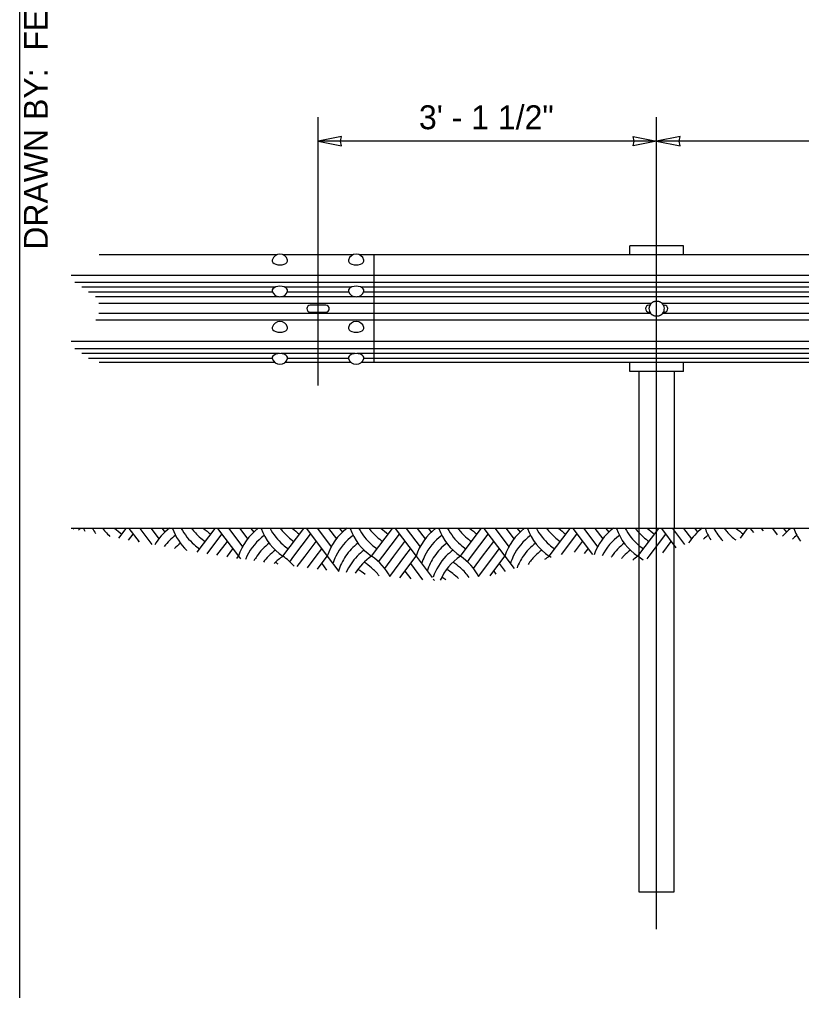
# Model space of a CAD drawing. Extents: x 99862 to 103680, y 99470 to 102076.
# Drawn here: x 99862 to 100385, y 100777 to 101426 of the extents above; entities that cross this region are included whole.
import ezdxf

# ---------------------------------------------------------------- set-up
doc = ezdxf.new("R2010")
doc.units = 0
for name, color, linetype in [('Level 1', 7, 'Continuous'), ('Level 14', 7, 'Continuous'), ('Level 15', 7, 'Continuous'), ('Level 2', 7, 'Continuous'), ('Level 20', 7, 'Continuous'), ('Level 27', 7, 'Continuous'), ('Level 4', 7, 'Continuous'), ('Level 62', 7, 'Continuous'), ('Level 7', 7, 'Continuous')]:
    doc.layers.add(name, color=color, linetype=linetype)

msp = doc.modelspace()

# ---------------------------------------------------------------- linework, layer by layer
at = {"layer": 'Level 1'}
msp.add_lwpolyline([(99862, 99999.5), (103151, 99999.5), (103151, 102075.5), (99862, 102075.5)], close=True, dxfattribs=at)
at = {"layer": 'Level 14'}
for p, q in [((100061.81, 101181.24), (100061.81, 101360.59)), ((100288.31, 100817.51), (100288.31, 101360.59)), ((102045.91, 101085.68), (99896.57, 101085.68)), ((99898.07, 101085.68), (99898.41, 101085.22)), ((99928.55, 101079.12), (99933.46, 101085.68)), ((99935.19, 101085.68), (99942.03, 101076.55)), ((99942.61, 101085.68), (99950.65, 101074.97)), ((99950.04, 101085.68), (99955.29, 101078.67)), ((99957.46, 101085.68), (99959.37, 101083.13)), ((99980.91, 101069.75), (99992.86, 101085.68)), ((99994.58, 101085.68), (100008.57, 101067.03)), ((100002.01, 101085.68), (100011.25, 101073.36)), ((100009.43, 101085.68), (100014.69, 101078.67)), ((100016.86, 101085.68), (100018.77, 101083.13)), ((100038.27, 101067.03), (100052.26, 101085.68)), ((100053.98, 101085.68), (100067.97, 101067.03)), ((100061.4, 101085.68), (100070.64, 101073.36)), ((100068.83, 101085.68), (100074.09, 101078.67)), ((100076.25, 101085.68), (100078.16, 101083.13)), ((100097.66, 101067.03), (100111.65, 101085.68)), ((100113.38, 101085.68), (100127.36, 101067.03)), ((100120.8, 101085.68), (100130.04, 101073.36)), ((100128.23, 101085.68), (100133.48, 101078.67)), ((100135.65, 101085.68), (100137.56, 101083.13)), ((100157.06, 101067.03), (100171.05, 101085.68)), ((100172.77, 101085.68), (100186.76, 101067.03)), ((100180.2, 101085.68), (100189.43, 101073.36)), ((100187.62, 101085.68), (100192.88, 101078.67)), ((100195.05, 101085.68), (100196.95, 101083.13)), ((100216.46, 101067.03), (100230.44, 101085.68)), ((100232.17, 101085.68), (100245.34, 101068.11)), ((100239.59, 101085.68), (100248.83, 101073.36)), ((100247.02, 101085.68), (100252.27, 101078.67)), ((100254.44, 101085.68), (100256.35, 101083.13)), ((100275.85, 101067.03), (100289.84, 101085.68)), ((100291.56, 101085.68), (100301.28, 101072.72)), ((100298.99, 101085.68), (100307.05, 101074.93)), ((100306.41, 101085.68), (100311.67, 101078.67)), ((100313.84, 101085.68), (100315.75, 101083.13)), ((100344.34, 101079.16), (100349.24, 101085.68)), ((100350.96, 101085.68), (100353.12, 101082.8)), ((100358.38, 101085.68), (100359.59, 101084.08)), ((100365.81, 101085.68), (100369.01, 101081.41)), ((100373.23, 101085.68), (100375.14, 101083.13)), ((99935.03, 101077.87), (99938.04, 101081.88)), ((99987.54, 101068.68), (99997.43, 101081.88)), ((100045.69, 101067.03), (100056.83, 101081.88)), ((100105.09, 101067.03), (100116.23, 101081.88)), ((100164.49, 101067.03), (100175.62, 101081.88)), ((100224.68, 101068.1), (100235.02, 101081.88)), ((100283.28, 101067.03), (100294.41, 101081.88)), ((99941.54, 101076.64), (99941.75, 101076.93)), ((99994.18, 101067.63), (100001.15, 101076.93)), ((100001.15, 101067.03), (100004.86, 101071.98)), ((100053.12, 101067.03), (100060.54, 101076.93)), ((100060.54, 101067.03), (100064.26, 101071.98)), ((100112.51, 101067.03), (100119.94, 101076.93)), ((100119.94, 101067.03), (100123.65, 101071.98)), ((100171.91, 101067.03), (100179.33, 101076.93)), ((100179.33, 101067.03), (100183.05, 101071.98)), ((100233.36, 101069.77), (100238.73, 101076.93)), ((100240.09, 101068.84), (100242.44, 101071.98)), ((100292.44, 101069.34), (100298.13, 101076.93)), ((100000.83, 101066.61), (100001.15, 101067.03)), ((100007.51, 101065.61), (100008.57, 101067.03)), ((100008.57, 101067.03), (100009.9, 101065.25)), ((100042.92, 101063.34), (100045.69, 101067.03)), ((100047.9, 101060.07), (100053.12, 101067.03)), ((100054.69, 101059.23), (100060.54, 101067.03)), ((100061.5, 101058.41), (100067.97, 101067.03)), ((100067.97, 101067.03), (100075.65, 101056.78)), ((100102.32, 101063.34), (100105.09, 101067.03)), ((100106.4, 101058.87), (100112.51, 101067.03)), ((100109.84, 101053.56), (100119.94, 101067.03)), ((100116.58, 101052.65), (100127.36, 101067.03)), ((100127.36, 101067.03), (100138.12, 101052.69)), ((100161.72, 101063.34), (100164.49, 101067.03)), ((100165.79, 101058.87), (100171.91, 101067.03)), ((100169.24, 101053.56), (100179.33, 101067.03)), ((100177, 101054.02), (100186.76, 101067.03)), ((100186.76, 101067.03), (100193, 101058.71)), ((100282.03, 101065.37), (100283.28, 101067.03)), ((100064.26, 101062.08), (100067.54, 101057.7)), ((100123.65, 101062.08), (100131.71, 101051.34)), ((100183.05, 101062.08), (100186.92, 101056.91)), ((100119.94, 101057.13), (100123.78, 101052.01)), ((100179.33, 101057.13), (100180.85, 101055.11)), ((100138.91, 101051.63), (100139.62, 101050.69))]:
    msp.add_line(p, q, dxfattribs=at)
for centre, start, end in [((99925.59, 101055.64), 126.9281, 129.9167), ((99940.44, 101098.22), 199.49222, 202.68252), ((99944.15, 101103.17), 207.73613, 213.8389), ((99947.86, 101108.12), 216.66402, 220.94161), ((99951.57, 101113.07), 226.78948, 236.09639), ((99984.99, 101055.64), 126.9281, 149.66125), ((99999.83, 101098.22), 199.49222, 226.66561), ((100003.55, 101103.17), 207.73613, 228.95992), ((100007.26, 101108.12), 216.66402, 220.94161), ((100010.97, 101113.07), 226.78948, 236.09639), ((100044.38, 101055.64), 126.9281, 162.3566), ((100059.23, 101098.22), 199.49222, 236.09639), ((100062.94, 101103.17), 207.73613, 228.95992), ((100066.66, 101108.12), 216.66402, 220.94161), ((100070.37, 101113.07), 226.78948, 236.09639), ((100103.78, 101055.64), 126.9281, 162.3566), ((100118.63, 101098.22), 199.49222, 236.09639), ((100122.34, 101103.17), 207.73613, 228.95992), ((100126.05, 101108.12), 216.66402, 220.94161), ((100129.76, 101113.07), 226.78948, 236.09639), ((100163.17, 101055.64), 126.9281, 162.3566), ((100178.02, 101098.22), 199.49222, 236.09639), ((100181.73, 101103.17), 207.73613, 228.95992), ((100185.45, 101108.12), 216.66402, 220.94161), ((100189.16, 101113.07), 226.78948, 236.09639), ((100222.57, 101055.64), 126.9281, 162.3566), ((100237.42, 101098.22), 199.49222, 236.09639), ((100241.13, 101103.17), 207.73613, 228.95992), ((100244.84, 101108.12), 216.66402, 220.94161), ((100248.55, 101113.07), 226.78948, 236.09639), ((100281.97, 101055.64), 126.9281, 160.86901), ((100296.81, 101098.22), 199.49222, 236.09639), ((100300.53, 101103.17), 207.73613, 228.95992), ((100304.24, 101108.12), 216.66402, 220.94161), ((100307.95, 101113.07), 226.78948, 236.09639), ((100341.36, 101055.64), 126.9281, 147.2728), ((100356.21, 101098.22), 199.49222, 212.62341), ((100359.92, 101103.17), 207.73613, 223.48992), ((100363.64, 101108.12), 216.66402, 220.94161), ((100367.35, 101113.07), 226.78948, 236.09639), ((100400.76, 101055.64), 126.9281, 138.73379), ((100415.61, 101098.22), 199.49222, 214.34907), ((99947.86, 101108.12), 220.94154, 227.7721), ((99988.7, 101050.69), 126.30625, 142.62545), ((100007.26, 101108.12), 220.94154, 236.09639), ((100048.09, 101050.69), 126.30625, 154.2266), ((100066.65, 101108.12), 220.94154, 236.09639), ((100107.49, 101050.69), 126.30625, 154.2266), ((100126.05, 101108.12), 220.94154, 236.09639), ((100166.89, 101050.69), 126.30625, 154.2266), ((100185.45, 101108.12), 220.94154, 236.09639), ((100226.28, 101050.69), 126.30625, 154.2266), ((100244.84, 101108.12), 220.94154, 236.09639), ((100285.68, 101050.69), 126.30625, 153.93888), ((100304.24, 101108.12), 220.94154, 236.09639), ((100345.07, 101050.69), 126.30625, 132.58834), ((100363.63, 101108.12), 220.94154, 233.54327), ((100404.47, 101050.69), 126.30625, 132.20032), ((99992.41, 101045.74), 127.1006, 135.05919), ((100003.55, 101103.17), 228.95986, 236.09639), ((100051.81, 101045.74), 127.1006, 145.49109), ((100062.94, 101103.17), 228.95986, 236.09639), ((100111.2, 101045.74), 127.1006, 145.49109), ((100122.34, 101103.17), 228.95986, 236.09639), ((100170.6, 101045.74), 127.1006, 145.49109), ((100181.73, 101103.17), 228.95986, 236.09639), ((100229.99, 101045.74), 127.1006, 145.49109), ((100241.13, 101103.17), 228.95986, 236.09639), ((100289.39, 101045.74), 127.1006, 145.49109), ((100300.53, 101103.17), 228.95986, 236.09639), ((99996.12, 101040.79), 126.331, 126.63745), ((100048.09, 101050.69), 154.22654, 158.00221), ((100051.81, 101045.74), 145.49102, 151.01331), ((100055.52, 101040.79), 135.71269, 143.64552), ((100055.52, 101040.79), 126.331, 135.71278), ((100059.23, 101035.84), 123.90361, 135.67245), ((100017.31, 101035.84), 40.68912, 56.09634), ((100107.49, 101050.69), 154.22654, 162.3566), ((100111.2, 101045.74), 145.49102, 162.3566), ((100114.91, 101040.79), 135.71269, 155.73788), ((100118.63, 101035.84), 123.90361, 148.29708), ((100114.91, 101040.79), 126.331, 135.71278), ((100076.7, 101035.84), 27.61697, 56.09634), ((100166.89, 101050.69), 154.22654, 162.3566), ((100170.6, 101045.74), 145.49102, 162.3566), ((100174.31, 101040.79), 135.71269, 161.09174), ((100178.02, 101035.84), 123.90361, 156.35656), ((100174.31, 101040.79), 126.331, 135.71278), ((100136.1, 101035.84), 27.7021, 56.09634), ((100226.28, 101050.69), 154.22654, 162.3566), ((100229.99, 101045.74), 145.49102, 158.86991), ((100233.71, 101040.79), 135.71269, 146.60048), ((100233.71, 101040.79), 126.331, 135.71278), ((100237.42, 101035.84), 123.90361, 129.68034), ((100195.5, 101035.84), 53.54319, 56.09634), ((100289.39, 101045.74), 145.49102, 146.71997), ((100293.1, 101040.79), 135.71269, 139.03751), ((100293.1, 101040.79), 126.331, 135.71278), ((100296.81, 101035.84), 123.90361, 130.60982), ((100254.89, 101035.84), 49.34985, 56.09634), ((100013.6, 101030.89), 55.16897, 58.54646), ((100072.99, 101030.89), 48.95968, 58.54646), ((100072.99, 101030.89), 37.87874, 48.95975), ((100132.39, 101030.89), 48.95968, 58.54646), ((100132.39, 101030.89), 35.50433, 48.95975), ((100069.28, 101025.94), 50.42511, 59.30215), ((100124.96, 101020.99), 53.63339, 58.48737), ((100128.68, 101025.94), 43.98671, 59.30215)]:
    msp.add_arc(centre, 37.58, start, end, dxfattribs=at)
at = {"layer": 'Level 15'}
for p, q in [((100288.31, 101344.59), (100061.81, 101344.59)), ((100738.31, 101344.59), (100288.31, 101344.59))]:
    msp.add_line(p, q, dxfattribs=at)
for points in [[(100061.81, 101344.59), (100077.53, 101341.51), (100076.81, 101344.59), (100077.53, 101347.68)], [(100288.31, 101344.59), (100272.58, 101341.51), (100273.31, 101344.59), (100272.58, 101347.68)], [(100288.31, 101344.59), (100304.03, 101341.51), (100303.31, 101344.59), (100304.03, 101347.68)]]:
    msp.add_lwpolyline(points, close=True, dxfattribs=at)
at = {"layer": 'Level 2'}
for p, q in [((100270.31, 101268.5), (100270.31, 101274.59)), ((100306.31, 101274.59), (100270.31, 101274.59)), ((100306.31, 101268.5), (100306.31, 101274.59)), ((100270.31, 101190.59), (100270.31, 101196.69)), ((100306.31, 101190.59), (100306.31, 101196.69)), ((100306.31, 101190.59), (100270.31, 101190.59))]:
    msp.add_line(p, q, dxfattribs=at)
at = {"layer": 'Level 27'}
for p, q in [((100034.41, 101268.68), (99915.45, 101268.68)), ((100085.41, 101268.68), (100038.21, 101268.68)), ((100933.93, 101268.68), (100089.21, 101268.68)), ((100099.31, 101196.69), (100099.31, 101268.68)), ((102061.41, 101254.83), (99896.57, 101254.83)), ((102058.94, 101250.08), (99899.11, 101250.08)), ((100032.86, 101246.86), (99903.69, 101246.86)), ((100031.44, 101243.63), (99908.28, 101243.63)), ((100035.83, 101240.4), (99912.85, 101240.4)), ((100086.83, 101240.4), (100036.79, 101240.4)), ((100083.86, 101246.86), (100039.76, 101246.86)), ((100082.44, 101243.63), (100041.18, 101243.63)), ((100935.35, 101240.4), (100087.79, 101240.4)), ((100932.38, 101246.86), (100090.76, 101246.86)), ((100930.96, 101243.63), (100092.18, 101243.63)), ((100284.46, 101235.95), (99915.09, 101235.95)), ((100734.37, 101235.95), (100292.26, 101235.95)), ((100284.31, 101229.41), (99915.09, 101229.41)), ((100734.22, 101229.41), (100292.42, 101229.41)), ((102045.2, 101224.96), (99913.17, 101224.96)), ((102061.41, 101210.53), (99896.57, 101210.53)), ((102058.94, 101205.78), (99899.11, 101205.78)), ((100035.71, 101202.56), (99903.69, 101202.56)), ((100086.71, 101202.56), (100036.91, 101202.56)), ((100935.23, 101202.56), (100087.91, 101202.56)), ((100031.2, 101199.33), (99908.27, 101199.33)), ((100032.81, 101196.69), (99915.47, 101196.69)), ((100083.81, 101196.69), (100039.8, 101196.69)), ((100082.2, 101199.33), (100041.42, 101199.33)), ((100932.34, 101196.69), (100090.8, 101196.69)), ((100930.72, 101199.33), (100092.42, 101199.33))]:
    msp.add_line(p, q, dxfattribs=at)
at = {"layer": 'Level 4'}
for p, q in [((100276.45, 101190.59), (100276.45, 101085.68)), ((100300.09, 101190.59), (100300.09, 101085.68)), ((100276.45, 101085.68), (100276.45, 100842.59)), ((100300.09, 100842.59), (100300.09, 101085.68)), ((100276.45, 100842.59), (100300.09, 100842.59))]:
    msp.add_line(p, q, dxfattribs=at)
at = {"layer": 'Level 7'}
for p, q in [((100041.4, 101265.12), (100041.4, 101265.12)), ((100082.21, 101265.12), (100082.21, 101265.12)), ((100067.06, 101234.84), (100056.56, 101234.84)), ((100283.73, 101234.84), (100283.12, 101234.84)), ((100293, 101234.84), (100293.62, 101234.84)), ((100056.56, 101230.34), (100067.06, 101230.34)), ((100283.12, 101230.34), (100283.73, 101230.34)), ((100284.36, 101229.35), (100284.36, 101229.35)), ((100293.62, 101230.34), (100293, 101230.34)), ((100041.4, 101220.1), (100041.4, 101220.09)), ((100082.21, 101220.09), (100082.22, 101220.1))]:
    msp.add_line(p, q, dxfattribs=at)
for centre, radius, start, end in [((100036.31, 101263.76), 5.27, 14.92454, 165.07546), ((100087.31, 101263.76), 5.27, 14.92454, 165.07546), ((100036.31, 101245.66), 5.27, 194.92454, 345.07546), ((100087.31, 101245.66), 5.27, 194.92454, 345.07546), ((100056.56, 101232.59), 2.25, 90, 270), ((100067.06, 101232.59), 2.25, 270, 90), ((100283.12, 101232.59), 2.25, 90, 270), ((100288.37, 101232.59), 5.15, 140.98001, 219.01876), ((100288.37, 101232.59), 5.15, 321.006, 47.40991), ((100293.62, 101232.59), 2.25, 270, 90), ((100036.31, 101218.74), 5.27, 14.92454, 165.07546), ((100087.31, 101218.74), 5.27, 14.92454, 165.07546), ((100036.31, 101200.64), 5.27, 194.92454, 345.07546), ((100087.31, 101200.64), 5.27, 194.92454, 345.07546)]:
    msp.add_arc(centre, radius, start, end, dxfattribs=at)
for centre, major_axis, ratio, start_param, end_param in [((100036.31, 101264.7), (5.15, 0), 0.558353, 2.993365, 6.431413), ((100087.31, 101264.7), (5.15, 0), 0.558353, 2.993365, 6.431413), ((100036.31, 101244.72), (-5.15, 0), 0.558352, 2.993855, 6.430923), ((100087.31, 101244.72), (-5.15, 0), 0.558352, 2.993855, 6.430923), ((100036.31, 101219.67), (-5.15, 0), 0.558352, 6.132899, 9.575065), ((100087.31, 101219.67), (-5.15, 0), 0.558352, 6.132899, 9.575065), ((100036.31, 101199.7), (-5.15, 0), 0.558352, 2.993855, 6.430923), ((100087.31, 101199.7), (-5.15, 0), 0.558352, 2.993855, 6.430923)]:
    msp.add_ellipse(centre, major_axis=major_axis, ratio=ratio, start_param=start_param, end_param=end_param, dxfattribs=at)
for points in [[(100284.36, 101235.83), (100284.7, 101236.25), (100285.12, 101236.62), (100285.58, 101236.9), (100286.04, 101237.18), (100286.55, 101237.39), (100287.07, 101237.51), (100287.63, 101237.65), (100288.23, 101237.69), (100288.81, 101237.65), (100289.4, 101237.6), (100289.98, 101237.46), (100290.52, 101237.22), (100291, 101237.02), (100291.46, 101236.73), (100291.85, 101236.38)], [(100292.37, 101229.35), (100292.04, 101228.93), (100291.62, 101228.57), (100291.16, 101228.29), (100290.7, 101228.01), (100290.2, 101227.8), (100289.67, 101227.67), (100289.11, 101227.54), (100288.52, 101227.49), (100287.94, 101227.53), (100287.35, 101227.58), (100286.76, 101227.72), (100286.22, 101227.95), (100285.68, 101228.19), (100285.18, 101228.52), (100284.75, 101228.93), (100284.61, 101229.06), (100284.48, 101229.2), (100284.36, 101229.35)]]:
    msp.add_open_spline(points, degree=3, dxfattribs=at)

# ---------------------------------------------------------------- texts
at = {"layer": 'Level 20'}
msp.add_text('3\' - 1 1/2"', height=16, dxfattribs=at).set_placement((100129.32, 101352.59))
at = {"layer": 'Level 62'}
msp.add_text('DRAWN BY:  FERN LIDDELL', height=16, rotation=90, dxfattribs=at).set_placement((99881, 101271.99))

doc.saveas('drawing.dxf')
